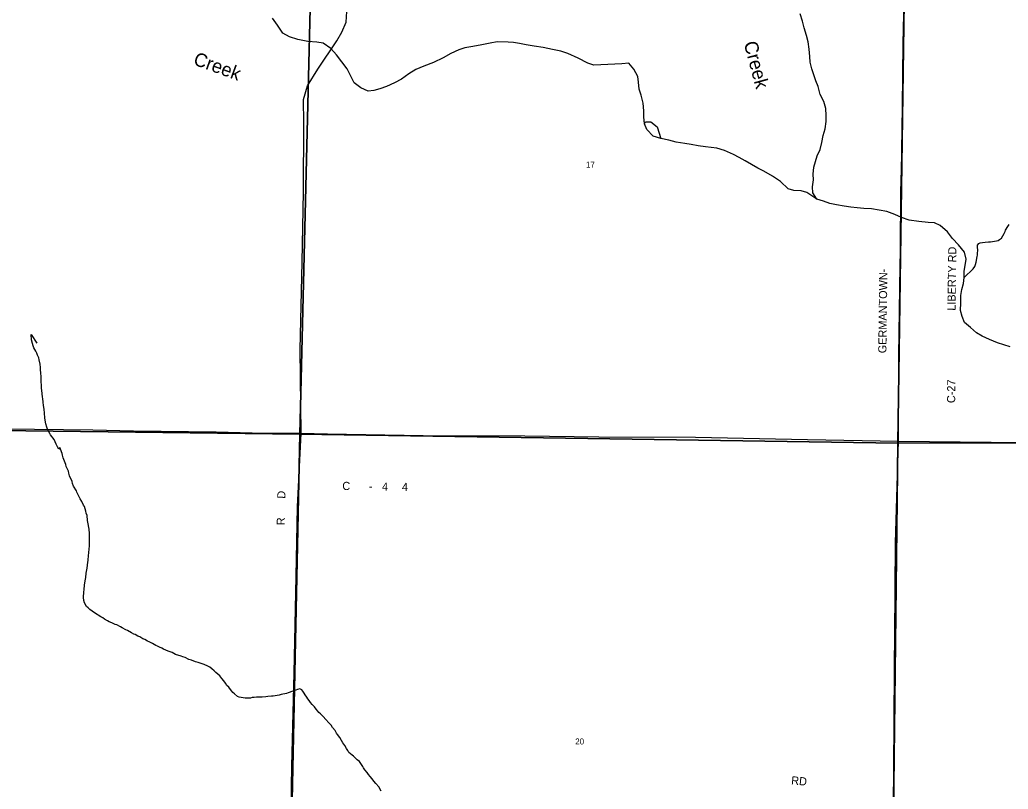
# Model space of a CAD drawing. Extents: x 1312308 to 1684953, y 460642 to 865172.
# Drawn here: x 1446100 to 1455224, y 621889 to 628989 of the extents above; entities that cross this region are included whole.
import ezdxf

# ---------------------------------------------------------------- set-up
doc = ezdxf.new("R2010")
doc.units = 0
for name, color, linetype in [('GM_X_County_Road', 7, 'Continuous'), ('GM_X_County_Road_Text', 7, 'Continuous'), ('GM_X_Minor_River', 7, 'Continuous'), ('GM_X_Minor_River_Text', 7, 'Continuous'), ('GM_X_Section', 7, 'Continuous'), ('GM_X_Section_Text', 7, 'Continuous'), ('GM_X_Township_Road', 7, 'Continuous'), ('GM_X_Township_Road_Text', 7, 'Continuous')]:
    doc.layers.add(name, color=color, linetype=linetype)

msp = doc.modelspace()

# ---------------------------------------------------------------- linework, layer by layer
at = {"layer": 'GM_X_County_Road'}
for points in [[(1454236.9, 627578.9), (1454246.2, 628185.5), (1454253.4, 628768.9), (1454262.7, 629179.7), (1454278.8, 629273.6), (1454360.3, 629422.2), (1454495, 629619.7), (1454582.8, 629780.1), (1454716.6, 630044.6), (1454898.5, 630434.2), (1454948.5, 630553.6), (1454971.6, 630633.4), (1454975.5, 630887.5), (1454972.6, 631254), (1454974.5, 631673.5)], [(1448594, 621127.5), (1448612.1, 622102.6), (1448631.5, 622959.2), (1448651.7, 623851.7), (1448662.3, 624495.5), (1448695.5, 625175.4), (1448689.2, 625947.2), (1448705.4, 626753), (1448718, 627400.4), (1448720.4, 628038), (1448719.3, 628254.6), (1448754.2, 628380.1), (1448849.9, 628534.4), (1449024.9, 628795.7), (1449071.9, 628874.4), (1449111.5, 628966.9), (1449119.1, 629065.1)], [(1454228.8, 626893.4), (1454233.7, 627369.6), (1454236.2, 627532.8), (1454236.9, 627578.9)], [(1454210.5, 625100.4), (1454214.3, 625890), (1454227, 626718), (1454228.4, 626849.4), (1454228.8, 626893.4)], [(1443383.2, 625252.4), (1444200.8, 625240.3), (1445060.5, 625228.9), (1445963.7, 625214.6), (1446775.5, 625203.9), (1447150.4, 625196.1), (1447911.5, 625185.4), (1448355.6, 625175.4), (1448695.5, 625175.4), (1448940.4, 625168.2), (1449822.9, 625153.9), (1450760.1, 625148.6), (1451445.5, 625141.4), (1452338, 625136.1), (1453371.5, 625116.4), (1454210.5, 625100.4), (1455352.9, 625087.9)]]:
    msp.add_lwpolyline(points, dxfattribs=at)
at = {"layer": 'GM_X_Minor_River'}
for points in [[(1453456.4, 627334), (1453365.6, 627394.8), (1453311.8, 627410.4), (1453245.5, 627414.3), (1453191.7, 627427.9), (1453121.2, 627496.1), (1453046.1, 627544.4), (1452967, 627590.8), (1452911.5, 627618.5), (1452854.1, 627652.2), (1452794.7, 627686), (1452739.3, 627717.7), (1452687.8, 627745.3), (1452604.4, 627781.8), (1452532.7, 627803.9), (1452428.5, 627816.8), (1452362.4, 627824.7), (1452296.4, 627836.6), (1452238.4, 627846.3), (1452158.4, 627860.6), (1452090.5, 627876.6), (1452016.6, 627892.7), (1451946.8, 627914.8), (1451888.2, 627976.7), (1451865.5, 628027.5), (1451859.3, 628093.9), (1451858.8, 628150.1), (1451852.6, 628218.6), (1451834.6, 628293.3), (1451818, 628350), (1451809.7, 628412.5), (1451803.1, 628464.9), (1451766.7, 628532.1), (1451720, 628589.7), (1451657.6, 628583.4), (1451397.9, 628568.6), (1451344.2, 628588.2), (1451255, 628634.9), (1451159.7, 628677.7), (1451094, 628697.7), (1451016.1, 628715.9), (1450932.1, 628732.3), (1450848.1, 628746.7), (1450774.1, 628758.9), (1450712.1, 628770.6), (1450658.1, 628780.2), (1450607.9, 628783.6), (1450505.5, 628784.5), (1450442.9, 628774.2), (1450364.1, 628758.4), (1450281.3, 628742.7), (1450208.5, 628728.6), (1450151.8, 628712.2), (1450078.5, 628678.1), (1450007.1, 628638), (1449919.5, 628594.3), (1449830.1, 628560.7), (1449754.9, 628528.6), (1449691.6, 628490.3), (1449623.9, 628440), (1449558.6, 628405.7), (1449483.4, 628373.7), (1449424.5, 628351.3), (1449367.8, 628334.8), (1449315.4, 628330.3), (1449247.9, 628360.3), (1449186.9, 628406.1), (1449150.7, 628479.4), (1449120.1, 628536.5), (1449073.6, 628600), (1449023.1, 628665.7), (1448972.4, 628723.3), (1448901.4, 628771.5), (1448841.3, 628781.2), (1448757.2, 628789.6), (1448665.2, 628806.2), (1448589.5, 628830.4), (1448528.1, 628866.3), (1448479.9, 628937.9), (1448431.4, 629003.5)], [(1455240.1, 625970.4), (1455182.3, 625990.1), (1455124.5, 626007.8), (1455051, 626038), (1454981.5, 626070.1), (1454930.1, 626099.6), (1454875.1, 626149.4), (1454820.1, 626195.1), (1454797.5, 626252), (1454783, 626306.6), (1454786.9, 626376.8), (1454784.7, 626445.1), (1454794.2, 626499), (1454811.8, 626554.8), (1454817.4, 626610.8), (1454816.9, 626669.1), (1454826.4, 626721), (1454834.1, 626781), (1454819.7, 626843.7), (1454765.3, 626911.5), (1454710.6, 626971.3), (1454662, 627030.9), (1454595.3, 627091), (1454543.8, 627116.5), (1454483.5, 627118.2), (1454399.3, 627126.6), (1454309.3, 627141.2), (1454239.6, 627163.3), (1454176, 627191.2), (1454104.4, 627219.3), (1453960.4, 627243.5), (1453892.2, 627247.4), (1453828, 627253.2), (1453769.9, 627260.9), (1453707.8, 627268.7), (1453637.8, 627280.7), (1453577.9, 627294.5), (1453518.2, 627314.2), (1453456.4, 627334), (1453419.8, 627393.3), (1453417.3, 627447.6), (1453425.1, 627511.6), (1453422.5, 627563.9), (1453428.2, 627628), (1453443.7, 627679.7), (1453459.2, 627733.5), (1453486.9, 627790.9), (1453502.8, 627856.7), (1453516.6, 627920.6), (1453534.4, 627982.3), (1453544.2, 628050.3), (1453543.8, 628106.5), (1453539.5, 628170.9), (1453521.1, 628233.6), (1453486.8, 628300.8), (1453468.6, 628371.6), (1453448, 628426.4), (1453410.8, 628535.9), (1453394.3, 628596.5), (1453391.8, 628650.8), (1453387.6, 628717.2), (1453377.3, 628783.7), (1453362.8, 628842.3), (1453340.7, 628913.2), (1453324.3, 628975.9), (1453302, 629044.8)], [(1451865.5, 628027.5), (1451874.6, 628047), (1451924.8, 628046.1), (1451982.2, 628000.8), (1452016.6, 627892.7)], [(1454817.4, 626610.8), (1454901, 626689.6), (1454915.7, 626713.3), (1454922.2, 626729.3), (1454928.8, 626753.2), (1454936.1, 626803.3), (1454938.5, 626817.4), (1454938.9, 626831.4), (1454941.7, 626861.5), (1454940.4, 626889.7), (1454940.9, 626909.8), (1454951.4, 626925.7), (1454965.6, 626931.3), (1454985.8, 626932.8), (1455010, 626936.3), (1455042.3, 626939.5), (1455058.5, 626941.1), (1455115, 626947.8), (1455129.2, 626953.5), (1455143.5, 626961.2), (1455162, 626974.8), (1455187.2, 627016.4), (1455195.7, 627034.3), (1455198.1, 627048.3), (1455219.1, 627082), (1455231.6, 627099.8)], [(1446206, 626071.3), (1446204.3, 626085.4), (1446256.6, 626003.7)], [(1447077.9, 623360.4), (1447046.2, 623379.2), (1447030.3, 623387.7), (1446996.5, 623404.6), (1446980.6, 623409), (1446950.8, 623425.8), (1446924.9, 623434.5), (1446909, 623443), (1446881.2, 623459.7), (1446865.4, 623470.2), (1446847.6, 623480.7), (1446788.1, 623518.3), (1446746.6, 623547.5), (1446730.9, 623562), (1446715.2, 623576.5), (1446695.9, 623609.1), (1446690.4, 623631.4), (1446689.1, 623657.6), (1446690.5, 623711.9), (1446693, 623729.9), (1446698.1, 623774.1), (1446705.6, 623828.2), (1446708, 623842.3), (1446713, 623882.4), (1446722.3, 623930.4), (1446727.7, 623984.6), (1446730.2, 624000.7), (1446735.4, 624048.8), (1446737.9, 624066.9), (1446741.1, 624111.1), (1446743.5, 624129.1), (1446744.6, 624171.3), (1446743, 624187.5), (1446744.6, 624247.8), (1446741.6, 624288.1), (1446738, 624304.3), (1446730.8, 624338.7), (1446725.6, 624369), (1446720.7, 624413.4), (1446713.3, 624437.7), (1446709.7, 624453.9), (1446696.7, 624496.4), (1446687, 624510.7), (1446673.7, 624543.3), (1446656.3, 624569.8), (1446635.2, 624610.6), (1446627.6, 624628.9), (1446624, 624643), (1446596.9, 624685.9), (1446587.5, 624710.3), (1446583.9, 624728.5), (1446559.1, 624779.4), (1446553.7, 624805.7), (1446548.1, 624823.9), (1446529.1, 624866.6), (1446523.6, 624886.9), (1446519.9, 624901.1), (1446501, 624945.8), (1446493.6, 624972.1), (1446490, 624988.3), (1446476.9, 625026.8), (1446469.2, 625041.1), (1446460.8, 625027.2), (1446447.3, 625049.7), (1446435.8, 625072.1), (1446416.8, 625114.8), (1446383.7, 625157.8), (1446376, 625172.1), (1446354.9, 625212.8), (1446349.3, 625229.1), (1446340, 625259.5), (1446332.9, 625295.8), (1446331.4, 625316), (1446328.5, 625360.3), (1446323.4, 625396.7), (1446320.2, 625428.9), (1446317, 625459.2), (1446311.8, 625493.5), (1446310.2, 625507.6), (1446305, 625541.9), (1446303.7, 625568.1), (1446300.2, 625588.3), (1446298.7, 625608.4), (1446297.9, 625656.7), (1446296.4, 625674.9), (1446297, 625697), (1446293.8, 625729.2), (1446290.6, 625763.5), (1446291, 625779.6), (1446287.8, 625811.8), (1446278.8, 625850.3), (1446275.3, 625870.5), (1446261.8, 625892.9), (1446256.2, 625911.2), (1446248.7, 625931.5), (1446229.3, 625962.1), (1446223.8, 625980.3), (1446218.3, 626002.6), (1446209.1, 626035), (1446209.4, 626049.1), (1446206, 626071.3)], [(1449137.9, 622229.4), (1449126.3, 622247.8), (1449116.7, 622266.2), (1449099.3, 622292.8), (1449081.8, 622317.3), (1449068.3, 622339.8), (1449052.9, 622366.4), (1449033.5, 622393), (1449023.8, 622407.3), (1449010.3, 622431.8), (1448984.9, 622458.6), (1448973.3, 622479), (1448953.8, 622501.6), (1448924.4, 622532.5), (1448898.9, 622561.3), (1448875.4, 622586), (1448861.6, 622596.4), (1448849.9, 622610.8), (1448836.3, 622629.3), (1448820.7, 622649.8), (1448797.1, 622670.5), (1448783.5, 622690.9), (1448769.9, 622709.4), (1448758.2, 622723.7), (1448750.6, 622740), (1448735, 622760.5), (1448725.3, 622774.8), (1448713.7, 622793.2), (1448704, 622807.6), (1448686.1, 622816.1), (1448663.8, 622808.6), (1448647.6, 622802.9), (1448621.1, 622793.5), (1448576.5, 622778.5), (1448562.2, 622772.8), (1448513.7, 622761.9), (1448493.4, 622756.3), (1448475.2, 622752.8), (1448438.8, 622747.6), (1448422.7, 622748), (1448390.4, 622744.8), (1448370.3, 622743.3), (1448336, 622740.1), (1448305.7, 622738.8), (1448285.6, 622737.3), (1448263.4, 622735.8), (1448245.2, 622734.2), (1448229, 622730.6), (1448215, 622730.9), (1448198.8, 622729.3), (1448180.7, 622729.8), (1448162.7, 622732.2), (1448142.6, 622734.7), (1448124.6, 622739.2), (1448108.7, 622745.6), (1448081.1, 622768.4), (1448067.3, 622780.8), (1448055.6, 622795.2), (1448043.9, 622809.6), (1448030.4, 622832), (1448010.6, 622846.6), (1447999.1, 622867), (1447983.6, 622889.5), (1447964, 622910.1), (1447946.5, 622934.7), (1447926.8, 622951.3), (1447909.1, 622967.8), (1447893.4, 622982.3), (1447871.7, 623000.9), (1447854, 623015.5), (1447834.1, 623026), (1447802.3, 623038.8), (1447782.3, 623045.4), (1447746.4, 623058.3), (1447722.4, 623064.9), (1447684.6, 623080), (1447660.6, 623086.6), (1447626.8, 623103.5), (1447604.8, 623110.1), (1447588.9, 623116.5), (1447537, 623131.8), (1447507.3, 623150.7), (1447469.4, 623163.7), (1447447.4, 623172.3), (1447427.5, 623180.8), (1447409.6, 623189.3), (1447389.8, 623199.8), (1447369.9, 623208.4), (1447356, 623216.8), (1447326.2, 623233.6), (1447294.4, 623248.4), (1447278.5, 623254.9), (1447252.7, 623271.6), (1447234.8, 623278.1), (1447207.1, 623294.8), (1447189.1, 623301.3), (1447165.3, 623316), (1447151.4, 623320.3), (1447129.5, 623332.9), (1447093.9, 623353.9), (1447077.9, 623360.4)], [(1449436.6, 621871.9), (1449413.5, 621912.8), (1449386.1, 621941.6), (1449366.6, 621964.2), (1449351, 621986.7), (1449333.5, 622007.3), (1449319.8, 622025.7), (1449306.2, 622042.2), (1449284.7, 622068.9), (1449273.1, 622085.2), (1449265.4, 622099.5), (1449234.4, 622144.6), (1449212.6, 622159.2), (1449181.3, 622194.2), (1449167.5, 622204.6), (1449137.9, 622229.4)]]:
    msp.add_lwpolyline(points, dxfattribs=at)
at = {"layer": 'GM_X_Section'}
for points in [[(1443490.8, 630551.1), (1448813.2, 630490.1), (1448684.1, 625165.1), (1443369.8, 625229.9), (1443469, 629861.6)], [(1448813.2, 630490.1), (1454281.7, 630438.2), (1454204, 625082.2), (1448684.1, 625165.1)], [(1454281.7, 630438.2), (1459585.8, 630367.6), (1459521.5, 625085.3), (1454204, 625082.2)], [(1443369.8, 625229.9), (1448684.1, 625165.1), (1448573.8, 619879.7), (1443287.6, 619943.9)], [(1448684.1, 625165.1), (1454204, 625082.2), (1454142, 619813.9), (1453924, 619812.3), (1448573.8, 619879.7)], [(1454204, 625082.2), (1459521.5, 625085.3), (1459424.8, 619777.8), (1454142, 619813.9)]]:
    msp.add_lwpolyline(points, close=True, dxfattribs=at)
at = {"layer": 'GM_X_Township_Road'}
for points in [[(1454174.3, 623040.7), (1454175.7, 623301), (1454183.2, 624163.6), (1454210.5, 625100.4)], [(1454144.7, 619838.2), (1454154.3, 620590.5), (1454162.1, 621198.4), (1454163.9, 621720.1), (1454171.4, 622494.5), (1454174.2, 623023.5), (1454174.3, 623040.7)]]:
    msp.add_lwpolyline(points, dxfattribs=at)

# ---------------------------------------------------------------- texts
at = {"layer": 'GM_X_County_Road_Text'}
for s, rotation, p in [('LIBERTY RD', 89.18146, (1454736.6, 626303.9)), ('GERMANTOWN-', 89.28507, (1454098.5, 625911.7)), ('C-27', 89.328, (1454733.3, 625451.5)), ('C', 359.07403, (1449076.5, 624650.8)), ('4', 359.08293, (1449443.1, 624644.9)), ('4', 359.09455, (1449626.5, 624641.9)), ('D', 87.20853, (1448550, 624568.5)), ('-', 359.07745, (1449321, 624646.8)), ('R', 88.96177, (1448545.6, 624324.6))]:
    msp.add_text(s, height=75, rotation=rotation, dxfattribs=at).set_placement(p)
at = {"layer": 'GM_X_Minor_River_Text'}
for height, rotation, p in [(125.01, 285.0004, (1452781.1, 628773.9)), (125, 339.97741, (1447693.4, 628578.3))]:
    msp.add_text('Creek', height=height, rotation=rotation, dxfattribs=at).set_placement(p)
at = {"layer": 'GM_X_Section_Text'}
for s, p in [('17', (1451325.7, 627624.7)), ('20', (1451226.7, 622302.4))]:
    msp.add_text(s, height=55.25, rotation=0.00001, dxfattribs=at).set_placement(p)
at = {"layer": 'GM_X_Township_Road_Text'}
msp.add_text('RD', height=75, rotation=354.58118, dxfattribs=at).set_placement((1453217.7, 621935.3))

doc.saveas('drawing.dxf')
